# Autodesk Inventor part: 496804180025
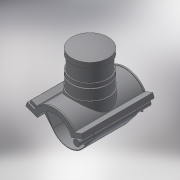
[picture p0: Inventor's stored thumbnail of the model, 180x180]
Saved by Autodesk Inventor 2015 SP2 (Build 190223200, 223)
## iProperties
Created: 2017-07
Part Number: 496804180025
Material: Generic
Description: PLASSON BALLOON SADDLE 180-2.1/2"
Document SubType Name: Modeling
Designer: KIM
Density: 1 g/cm^3
Appearance: Default
Author: KIM
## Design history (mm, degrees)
derived "496804.ipt"
feature "Solid1::496804.ipt"
feature "Solid2::496804.ipt"
tag "TaggingFeature1"
body "Solid1"
body "Solid2"
other parameters: "d1" = 207, "d4" = 176, "d5" = 0, "d40" = 107.64, "d96" = 211.14, "d97" = 3.52, "d98" = 0, "d120" = 100 deg, "d121" = 24.228, "d122" = 40 deg, "d123" = 414, "d124" = 124.2, "d126" = 0, "d143" = 185.4, "d145" = 20.76923, "d149" = 2.7, "d150" = 22.84615, "d153" = 176, "d154" = 0, "d159" = 5.4, "d161" = 2.7, "d162" = 105.6, "d163" = 0, "d168" = 94.09091, "d170" = 2.7, "d172" = 0, "d173" = 1, "d176" = 40 deg, "d177" = 14.4, "d180" = 0, "d185" = 57.2, "d186" = 57.2, "d187" = 103.5, "d188" = 8.1, "d190" = 0, "d191" = 165.6, "d193" = 5.4, "d194" = 4.4, "d195" = 90 deg, "d197" = 0, "d199" = 0, "d200" = 105, "d201" = 1, "d203" = 94.5, "d204" = 97.65, "d205" = 85.5, "d206" = 1.8, "d207" = 52.5, "d208" = 42, "d209" = 84, "d210" = 21, "d214" = 207, "d216" = 0, "d217" = 91, "d218" = 55, "d219" = 36, "d220" = 15.98, "d221" = 20 deg, "d223" = 11.36702, "d224" = 5.68351, "d226" = 0, "d227" = -17.6, "d228" = 2.7, "d229" = 39.6, "B_" = 182, "H_" = 105, "L_" = 176, "d_t" = 6, "d148" = 2.7, "d160" = 2.7, "d169" = 2.7, "d192" = 5.4, "d222" = 14.20877
